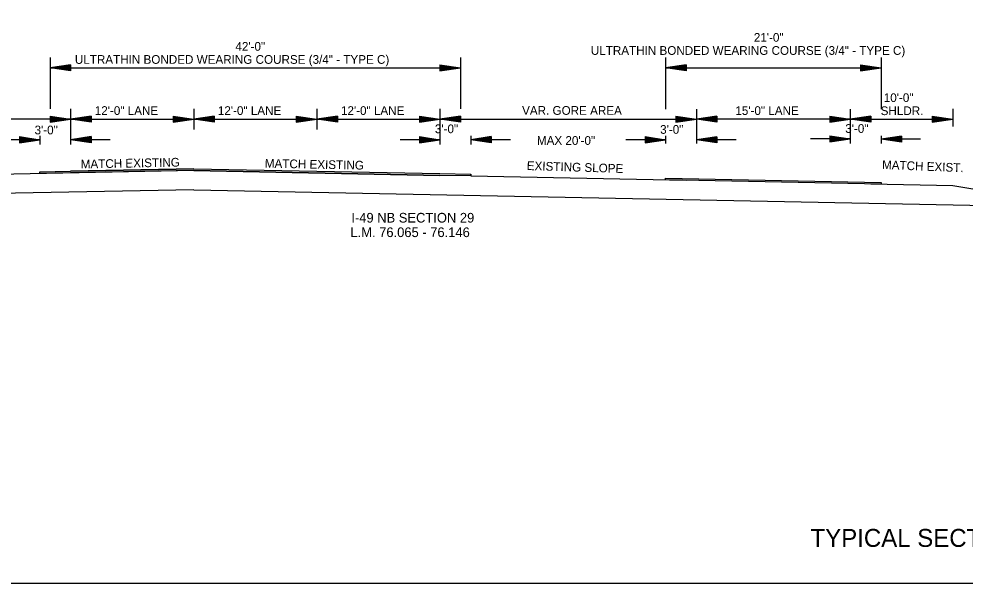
# Model space of a CAD drawing. Extents: x 2261938 to 2263136, y -3124572 to -3124216.
# Drawn here: x 2262374.3 to 2262466.5, y -3124556.1 to -3124501.1 of the extents above; entities that cross this region are included whole.
import ezdxf

# ---------------------------------------------------------------- set-up
doc = ezdxf.new("R2010")
doc.units = 0
for name, color, linetype in [('DSN_DRFT_Common-Annotations', 7, 'Continuous'), ('DSN_DRFT_Common-Line', 7, 'Continuous'), ('DSN_DRFT_Dimension', 7, 'Continuous'), ('SHET_Border-Text', 7, 'Continuous')]:
    doc.layers.add(name, color=color, linetype=linetype)

msp = doc.modelspace()

# ---------------------------------------------------------------- linework, layer by layer
at = {"layer": 'DSN_DRFT_Common-Line'}
for p, q in [((2262377.333, -3124504.876), (2262377.333, -3124509.876)), ((2262417.333, -3124504.876), (2262417.333, -3124509.876)), ((2262437.332, -3124504.876), (2262437.332, -3124509.896)), ((2262458.334, -3124504.876), (2262458.334, -3124509.896)), ((2262379.333, -3124509.876), (2262379.333, -3124513.335)), ((2262391.333, -3124509.876), (2262391.333, -3124511.876)), ((2262403.333, -3124509.876), (2262403.333, -3124511.876)), ((2262415.333, -3124509.876), (2262415.333, -3124513.335)), ((2262465.333, -3124509.876), (2262465.333, -3124511.579)), ((2262440.333, -3124509.896), (2262440.333, -3124513.261)), ((2262455.333, -3124509.896), (2262455.333, -3124513.261)), ((2262376.333, -3124512.495), (2262376.333, -3124513.335)), ((2262418.333, -3124512.495), (2262418.333, -3124513.335)), ((2262437.332, -3124512.495), (2262437.332, -3124513.261)), ((2262458.334, -3124512.495), (2262458.334, -3124513.261)), ((2262391.333, -3124515.876), (2262363.333, -3124516.436)), ((2262391.333, -3124515.71), (2262379.333, -3124515.95)), ((2262391.333, -3124515.71), (2262415.333, -3124516.19)), ((2262391.333, -3124515.876), (2262415.333, -3124516.356)), ((2262418.333, -3124516.416), (2262418.333, -3124516.25)), ((2262418.333, -3124516.416), (2262439.333, -3124516.836)), ((2262457.334, -3124517.191), (2262465.333, -3124517.351)), ((2262391.333, -3124517.751), (2262361.333, -3124518.351)), ((2262391.333, -3124517.751), (2262478.157, -3124519.488)), ((2262465.333, -3124517.351), (2262485.333, -3124520.684))]:
    msp.add_line(p, q, dxfattribs=at)
for points in [[(2262328.106, -3124446.104), (2262328.106, -3124556.104), (2262498.106, -3124556.104), (2262498.106, -3124446.104)], [(2262415.333, -3124516.356), (2262391.333, -3124515.876), (2262379.333, -3124516.116), (2262376.333, -3124516.176), (2262376.333, -3124516.01), (2262379.333, -3124515.95), (2262391.333, -3124515.71), (2262415.333, -3124516.19), (2262418.333, -3124516.25), (2262418.333, -3124516.416)], [(2262458.334, -3124517.211), (2262437.332, -3124516.796), (2262437.332, -3124516.796), (2262437.332, -3124516.796), (2262437.332, -3124516.63), (2262437.332, -3124516.63), (2262437.332, -3124516.63), (2262458.334, -3124517.044), (2262458.334, -3124517.044), (2262458.334, -3124517.211)]]:
    msp.add_lwpolyline(points, close=True, dxfattribs=at)
at = {"layer": 'DSN_DRFT_Dimension'}
for p, q in [((2262379.333, -3124505.576), (2262377.333, -3124505.876)), ((2262379.333, -3124506.176), (2262377.333, -3124505.876)), ((2262377.333, -3124505.876), (2262417.333, -3124505.876)), ((2262379.333, -3124505.626), (2262377.667, -3124505.876)), ((2262379.333, -3124506.126), (2262377.667, -3124505.876)), ((2262379.333, -3124505.677), (2262378.011, -3124505.876)), ((2262379.333, -3124506.075), (2262378.011, -3124505.876)), ((2262379.333, -3124505.727), (2262378.344, -3124505.876)), ((2262379.333, -3124506.025), (2262378.344, -3124505.876)), ((2262379.333, -3124505.779), (2262378.683, -3124505.876)), ((2262379.333, -3124505.974), (2262378.683, -3124505.876)), ((2262379.333, -3124505.829), (2262379.017, -3124505.876)), ((2262379.333, -3124505.923), (2262379.017, -3124505.876)), ((2262379.333, -3124505.576), (2262379.333, -3124506.176)), ((2262415.333, -3124505.576), (2262417.333, -3124505.876)), ((2262415.333, -3124505.576), (2262415.333, -3124506.176)), ((2262415.333, -3124505.626), (2262416.999, -3124505.876)), ((2262415.333, -3124505.677), (2262416.655, -3124505.876)), ((2262415.333, -3124505.727), (2262416.322, -3124505.876)), ((2262415.333, -3124505.779), (2262415.983, -3124505.876)), ((2262415.333, -3124505.829), (2262415.649, -3124505.876)), ((2262415.333, -3124506.176), (2262417.333, -3124505.876)), ((2262415.333, -3124505.974), (2262415.983, -3124505.876)), ((2262415.333, -3124506.075), (2262416.655, -3124505.876)), ((2262415.333, -3124506.126), (2262416.999, -3124505.876)), ((2262415.333, -3124506.025), (2262416.322, -3124505.876)), ((2262415.333, -3124505.923), (2262415.649, -3124505.876)), ((2262439.332, -3124505.576), (2262437.332, -3124505.876)), ((2262437.332, -3124505.876), (2262458.334, -3124505.876)), ((2262439.332, -3124506.176), (2262437.332, -3124505.876)), ((2262439.332, -3124505.626), (2262437.666, -3124505.876)), ((2262439.332, -3124506.126), (2262437.666, -3124505.876)), ((2262439.332, -3124505.677), (2262438.01, -3124505.876)), ((2262439.332, -3124506.075), (2262438.01, -3124505.876)), ((2262439.332, -3124505.727), (2262438.343, -3124505.876)), ((2262439.332, -3124506.025), (2262438.343, -3124505.876)), ((2262439.332, -3124505.779), (2262438.682, -3124505.876)), ((2262439.332, -3124505.974), (2262438.682, -3124505.876)), ((2262439.332, -3124505.829), (2262439.016, -3124505.876)), ((2262439.332, -3124505.923), (2262439.016, -3124505.876)), ((2262439.332, -3124505.576), (2262439.332, -3124506.176)), ((2262456.334, -3124505.576), (2262458.334, -3124505.876)), ((2262456.334, -3124505.576), (2262456.334, -3124506.176)), ((2262456.334, -3124505.626), (2262458, -3124505.876)), ((2262456.334, -3124505.677), (2262457.656, -3124505.876)), ((2262456.334, -3124505.727), (2262457.323, -3124505.876)), ((2262456.334, -3124505.779), (2262456.984, -3124505.876)), ((2262456.334, -3124505.829), (2262456.65, -3124505.876)), ((2262456.334, -3124506.176), (2262458.334, -3124505.876)), ((2262456.334, -3124505.974), (2262456.984, -3124505.876)), ((2262456.334, -3124506.075), (2262457.656, -3124505.876)), ((2262456.334, -3124506.126), (2262458, -3124505.876)), ((2262456.334, -3124506.025), (2262457.323, -3124505.876)), ((2262456.334, -3124505.923), (2262456.65, -3124505.876)), ((2262377.333, -3124510.576), (2262379.333, -3124510.876)), ((2262377.333, -3124510.576), (2262377.333, -3124511.176)), ((2262377.333, -3124510.626), (2262378.999, -3124510.876)), ((2262377.333, -3124510.677), (2262378.655, -3124510.876)), ((2262377.333, -3124510.727), (2262378.322, -3124510.876)), ((2262377.333, -3124510.779), (2262377.983, -3124510.876)), ((2262381.333, -3124510.576), (2262379.333, -3124510.876)), ((2262381.333, -3124510.626), (2262379.667, -3124510.876)), ((2262381.333, -3124510.677), (2262380.011, -3124510.876)), ((2262381.333, -3124510.727), (2262380.344, -3124510.876)), ((2262381.333, -3124510.779), (2262380.683, -3124510.876)), ((2262381.333, -3124510.576), (2262381.333, -3124511.176)), ((2262389.333, -3124510.576), (2262391.333, -3124510.876)), ((2262389.333, -3124510.576), (2262389.333, -3124511.176)), ((2262389.333, -3124510.626), (2262390.999, -3124510.876)), ((2262389.333, -3124510.677), (2262390.655, -3124510.876)), ((2262389.333, -3124510.727), (2262390.322, -3124510.876)), ((2262389.333, -3124510.779), (2262389.983, -3124510.876)), ((2262393.333, -3124510.576), (2262391.333, -3124510.876)), ((2262393.333, -3124510.626), (2262391.667, -3124510.876)), ((2262393.333, -3124510.677), (2262392.011, -3124510.876)), ((2262393.333, -3124510.727), (2262392.344, -3124510.876)), ((2262393.333, -3124510.779), (2262392.683, -3124510.876)), ((2262393.333, -3124510.576), (2262393.333, -3124511.176)), ((2262401.333, -3124510.576), (2262403.333, -3124510.876)), ((2262401.333, -3124510.576), (2262401.333, -3124511.176)), ((2262401.333, -3124510.626), (2262402.999, -3124510.876)), ((2262401.333, -3124510.677), (2262402.655, -3124510.876)), ((2262401.333, -3124510.727), (2262402.322, -3124510.876)), ((2262401.333, -3124510.779), (2262401.983, -3124510.876)), ((2262405.333, -3124510.576), (2262403.333, -3124510.876)), ((2262405.333, -3124510.626), (2262403.667, -3124510.876)), ((2262405.333, -3124510.677), (2262404.011, -3124510.876)), ((2262405.333, -3124510.727), (2262404.344, -3124510.876)), ((2262405.333, -3124510.779), (2262404.683, -3124510.876)), ((2262405.333, -3124510.576), (2262405.333, -3124511.176)), ((2262413.333, -3124510.576), (2262415.333, -3124510.876)), ((2262413.333, -3124510.576), (2262413.333, -3124511.176)), ((2262413.333, -3124510.626), (2262414.999, -3124510.876)), ((2262413.333, -3124510.677), (2262414.655, -3124510.876)), ((2262413.333, -3124510.727), (2262414.322, -3124510.876)), ((2262413.333, -3124510.779), (2262413.983, -3124510.876)), ((2262417.333, -3124510.576), (2262415.333, -3124510.876)), ((2262417.333, -3124510.626), (2262415.667, -3124510.876)), ((2262417.333, -3124510.677), (2262416.011, -3124510.876)), ((2262417.333, -3124510.727), (2262416.344, -3124510.876)), ((2262417.333, -3124510.779), (2262416.683, -3124510.876)), ((2262417.333, -3124510.576), (2262417.333, -3124511.176)), ((2262438.333, -3124510.576), (2262440.333, -3124510.876)), ((2262438.333, -3124510.576), (2262438.333, -3124511.176)), ((2262438.333, -3124510.626), (2262439.999, -3124510.876)), ((2262438.333, -3124510.677), (2262439.655, -3124510.876)), ((2262438.333, -3124510.727), (2262439.322, -3124510.876)), ((2262438.333, -3124510.779), (2262438.983, -3124510.876)), ((2262442.333, -3124510.576), (2262440.333, -3124510.876)), ((2262442.333, -3124510.626), (2262440.667, -3124510.876)), ((2262442.333, -3124510.677), (2262441.011, -3124510.876)), ((2262442.333, -3124510.727), (2262441.344, -3124510.876)), ((2262442.333, -3124510.779), (2262441.683, -3124510.876)), ((2262442.333, -3124510.576), (2262442.333, -3124511.176)), ((2262453.333, -3124510.576), (2262455.333, -3124510.876)), ((2262453.333, -3124510.576), (2262453.333, -3124511.176)), ((2262453.333, -3124510.626), (2262454.999, -3124510.876)), ((2262453.333, -3124510.677), (2262454.655, -3124510.876)), ((2262453.333, -3124510.727), (2262454.322, -3124510.876)), ((2262453.333, -3124510.779), (2262453.983, -3124510.876)), ((2262457.333, -3124510.576), (2262455.333, -3124510.876)), ((2262457.333, -3124510.626), (2262455.667, -3124510.876)), ((2262457.333, -3124510.677), (2262456.011, -3124510.876)), ((2262457.333, -3124510.727), (2262456.344, -3124510.876)), ((2262457.333, -3124510.779), (2262456.683, -3124510.876)), ((2262457.333, -3124510.576), (2262457.333, -3124511.176)), ((2262463.333, -3124510.576), (2262465.333, -3124510.876)), ((2262463.333, -3124510.576), (2262463.333, -3124511.176)), ((2262463.333, -3124510.626), (2262464.999, -3124510.876)), ((2262463.333, -3124510.677), (2262464.655, -3124510.876)), ((2262463.333, -3124510.727), (2262464.322, -3124510.876)), ((2262463.333, -3124510.779), (2262463.983, -3124510.876)), ((2262379.333, -3124510.876), (2262361.333, -3124510.876)), ((2262377.333, -3124510.829), (2262377.649, -3124510.876)), ((2262377.333, -3124511.176), (2262379.333, -3124510.876)), ((2262377.333, -3124510.974), (2262377.983, -3124510.876)), ((2262377.333, -3124511.075), (2262378.655, -3124510.876)), ((2262377.333, -3124511.126), (2262378.999, -3124510.876)), ((2262377.333, -3124511.025), (2262378.322, -3124510.876)), ((2262377.333, -3124510.923), (2262377.649, -3124510.876)), ((2262379.333, -3124510.876), (2262391.333, -3124510.876)), ((2262381.333, -3124511.176), (2262379.333, -3124510.876)), ((2262381.333, -3124511.126), (2262379.667, -3124510.876)), ((2262381.333, -3124511.075), (2262380.011, -3124510.876)), ((2262381.333, -3124511.025), (2262380.344, -3124510.876)), ((2262381.333, -3124510.974), (2262380.683, -3124510.876)), ((2262381.333, -3124510.829), (2262381.017, -3124510.876)), ((2262381.333, -3124510.923), (2262381.017, -3124510.876)), ((2262389.333, -3124510.829), (2262389.649, -3124510.876)), ((2262389.333, -3124511.176), (2262391.333, -3124510.876)), ((2262389.333, -3124510.974), (2262389.983, -3124510.876)), ((2262389.333, -3124511.075), (2262390.655, -3124510.876)), ((2262389.333, -3124511.126), (2262390.999, -3124510.876)), ((2262389.333, -3124511.025), (2262390.322, -3124510.876)), ((2262389.333, -3124510.923), (2262389.649, -3124510.876)), ((2262391.333, -3124510.876), (2262403.333, -3124510.876)), ((2262393.333, -3124511.176), (2262391.333, -3124510.876)), ((2262393.333, -3124511.126), (2262391.667, -3124510.876)), ((2262393.333, -3124511.075), (2262392.011, -3124510.876)), ((2262393.333, -3124511.025), (2262392.344, -3124510.876)), ((2262393.333, -3124510.974), (2262392.683, -3124510.876)), ((2262393.333, -3124510.829), (2262393.017, -3124510.876)), ((2262393.333, -3124510.923), (2262393.017, -3124510.876)), ((2262401.333, -3124510.829), (2262401.649, -3124510.876)), ((2262401.333, -3124511.176), (2262403.333, -3124510.876)), ((2262401.333, -3124510.974), (2262401.983, -3124510.876)), ((2262401.333, -3124511.075), (2262402.655, -3124510.876)), ((2262401.333, -3124511.126), (2262402.999, -3124510.876)), ((2262401.333, -3124511.025), (2262402.322, -3124510.876)), ((2262401.333, -3124510.923), (2262401.649, -3124510.876)), ((2262403.333, -3124510.876), (2262415.333, -3124510.876)), ((2262405.333, -3124511.176), (2262403.333, -3124510.876)), ((2262405.333, -3124511.126), (2262403.667, -3124510.876)), ((2262405.333, -3124511.075), (2262404.011, -3124510.876)), ((2262405.333, -3124511.025), (2262404.344, -3124510.876)), ((2262405.333, -3124510.974), (2262404.683, -3124510.876)), ((2262405.333, -3124510.829), (2262405.017, -3124510.876)), ((2262405.333, -3124510.923), (2262405.017, -3124510.876)), ((2262413.333, -3124510.829), (2262413.649, -3124510.876)), ((2262413.333, -3124511.176), (2262415.333, -3124510.876)), ((2262413.333, -3124510.974), (2262413.983, -3124510.876)), ((2262413.333, -3124511.075), (2262414.655, -3124510.876)), ((2262413.333, -3124511.126), (2262414.999, -3124510.876)), ((2262413.333, -3124511.025), (2262414.322, -3124510.876)), ((2262413.333, -3124510.923), (2262413.649, -3124510.876)), ((2262415.333, -3124510.876), (2262440.333, -3124510.876)), ((2262417.333, -3124511.176), (2262415.333, -3124510.876)), ((2262417.333, -3124511.126), (2262415.667, -3124510.876)), ((2262417.333, -3124511.075), (2262416.011, -3124510.876)), ((2262417.333, -3124511.025), (2262416.344, -3124510.876)), ((2262417.333, -3124510.974), (2262416.683, -3124510.876)), ((2262417.333, -3124510.829), (2262417.017, -3124510.876)), ((2262417.333, -3124510.923), (2262417.017, -3124510.876)), ((2262438.333, -3124510.829), (2262438.649, -3124510.876)), ((2262438.333, -3124511.176), (2262440.333, -3124510.876)), ((2262438.333, -3124510.974), (2262438.983, -3124510.876)), ((2262438.333, -3124511.075), (2262439.655, -3124510.876)), ((2262438.333, -3124511.126), (2262439.999, -3124510.876)), ((2262438.333, -3124511.025), (2262439.322, -3124510.876)), ((2262438.333, -3124510.923), (2262438.649, -3124510.876)), ((2262455.333, -3124510.876), (2262440.333, -3124510.876)), ((2262442.333, -3124511.176), (2262440.333, -3124510.876)), ((2262442.333, -3124511.126), (2262440.667, -3124510.876)), ((2262442.333, -3124511.075), (2262441.011, -3124510.876)), ((2262442.333, -3124511.025), (2262441.344, -3124510.876)), ((2262442.333, -3124510.974), (2262441.683, -3124510.876)), ((2262442.333, -3124510.829), (2262442.017, -3124510.876)), ((2262442.333, -3124510.923), (2262442.017, -3124510.876)), ((2262453.333, -3124510.829), (2262453.649, -3124510.876)), ((2262453.333, -3124511.176), (2262455.333, -3124510.876)), ((2262453.333, -3124510.974), (2262453.983, -3124510.876)), ((2262453.333, -3124511.075), (2262454.655, -3124510.876)), ((2262453.333, -3124511.126), (2262454.999, -3124510.876)), ((2262453.333, -3124511.025), (2262454.322, -3124510.876)), ((2262453.333, -3124510.923), (2262453.649, -3124510.876)), ((2262455.333, -3124510.876), (2262465.333, -3124510.876)), ((2262457.333, -3124511.176), (2262455.333, -3124510.876)), ((2262457.333, -3124511.126), (2262455.667, -3124510.876)), ((2262457.333, -3124511.075), (2262456.011, -3124510.876)), ((2262457.333, -3124511.025), (2262456.344, -3124510.876)), ((2262457.333, -3124510.974), (2262456.683, -3124510.876)), ((2262457.333, -3124510.829), (2262457.017, -3124510.876)), ((2262457.333, -3124510.923), (2262457.017, -3124510.876)), ((2262463.333, -3124510.829), (2262463.649, -3124510.876)), ((2262463.333, -3124511.176), (2262465.333, -3124510.876)), ((2262463.333, -3124510.974), (2262463.983, -3124510.876)), ((2262463.333, -3124511.075), (2262464.655, -3124510.876)), ((2262463.333, -3124511.126), (2262464.999, -3124510.876)), ((2262463.333, -3124511.025), (2262464.322, -3124510.876)), ((2262463.333, -3124510.923), (2262463.649, -3124510.876)), ((2262374.333, -3124512.576), (2262376.333, -3124512.876)), ((2262374.333, -3124512.576), (2262374.333, -3124513.176)), ((2262374.333, -3124512.626), (2262375.999, -3124512.876)), ((2262381.333, -3124512.576), (2262379.333, -3124512.876)), ((2262381.333, -3124512.626), (2262379.667, -3124512.876)), ((2262381.333, -3124512.576), (2262381.333, -3124513.176)), ((2262413.333, -3124512.576), (2262415.333, -3124512.876)), ((2262413.333, -3124512.576), (2262413.333, -3124513.176)), ((2262413.333, -3124512.626), (2262414.999, -3124512.876)), ((2262420.333, -3124512.576), (2262418.333, -3124512.876)), ((2262420.333, -3124512.626), (2262418.667, -3124512.876)), ((2262420.333, -3124512.576), (2262420.333, -3124513.176)), ((2262435.332, -3124512.576), (2262437.332, -3124512.876)), ((2262435.332, -3124512.576), (2262435.332, -3124513.176)), ((2262435.332, -3124512.626), (2262436.998, -3124512.876)), ((2262442.333, -3124512.596), (2262440.333, -3124512.896)), ((2262442.333, -3124512.646), (2262440.667, -3124512.896)), ((2262442.333, -3124512.596), (2262442.333, -3124513.196)), ((2262453.333, -3124512.502), (2262455.333, -3124512.802)), ((2262453.333, -3124512.502), (2262453.333, -3124513.102)), ((2262453.333, -3124512.552), (2262454.999, -3124512.802)), ((2262453.333, -3124512.603), (2262454.655, -3124512.802)), ((2262453.333, -3124512.653), (2262454.322, -3124512.802)), ((2262460.334, -3124512.522), (2262458.334, -3124512.822)), ((2262460.334, -3124512.572), (2262458.668, -3124512.822)), ((2262460.334, -3124512.623), (2262459.012, -3124512.822)), ((2262460.334, -3124512.522), (2262460.334, -3124513.122)), ((2262376.333, -3124512.876), (2262372.468, -3124512.876)), ((2262374.333, -3124512.677), (2262375.655, -3124512.876)), ((2262374.333, -3124512.727), (2262375.322, -3124512.876)), ((2262374.333, -3124512.779), (2262374.983, -3124512.876)), ((2262374.333, -3124512.829), (2262374.649, -3124512.876)), ((2262374.333, -3124513.176), (2262376.333, -3124512.876)), ((2262374.333, -3124512.974), (2262374.983, -3124512.876)), ((2262374.333, -3124513.075), (2262375.655, -3124512.876)), ((2262374.333, -3124513.126), (2262375.999, -3124512.876)), ((2262374.333, -3124513.025), (2262375.322, -3124512.876)), ((2262374.333, -3124512.923), (2262374.649, -3124512.876)), ((2262381.333, -3124513.176), (2262379.333, -3124512.876)), ((2262383.198, -3124512.876), (2262379.333, -3124512.876)), ((2262381.333, -3124513.126), (2262379.667, -3124512.876)), ((2262381.333, -3124512.677), (2262380.011, -3124512.876)), ((2262381.333, -3124513.075), (2262380.011, -3124512.876)), ((2262381.333, -3124512.727), (2262380.344, -3124512.876)), ((2262381.333, -3124513.025), (2262380.344, -3124512.876)), ((2262381.333, -3124512.779), (2262380.683, -3124512.876)), ((2262381.333, -3124512.974), (2262380.683, -3124512.876)), ((2262381.333, -3124512.829), (2262381.017, -3124512.876)), ((2262381.333, -3124512.923), (2262381.017, -3124512.876)), ((2262415.333, -3124512.876), (2262411.468, -3124512.876)), ((2262413.333, -3124512.677), (2262414.655, -3124512.876)), ((2262413.333, -3124512.727), (2262414.322, -3124512.876)), ((2262413.333, -3124512.779), (2262413.983, -3124512.876)), ((2262413.333, -3124512.829), (2262413.649, -3124512.876)), ((2262413.333, -3124513.176), (2262415.333, -3124512.876)), ((2262413.333, -3124512.974), (2262413.983, -3124512.876)), ((2262413.333, -3124513.075), (2262414.655, -3124512.876)), ((2262413.333, -3124513.126), (2262414.999, -3124512.876)), ((2262413.333, -3124513.025), (2262414.322, -3124512.876)), ((2262413.333, -3124512.923), (2262413.649, -3124512.876)), ((2262420.333, -3124513.176), (2262418.333, -3124512.876)), ((2262422.198, -3124512.876), (2262418.333, -3124512.876)), ((2262420.333, -3124513.126), (2262418.667, -3124512.876)), ((2262420.333, -3124512.677), (2262419.011, -3124512.876)), ((2262420.333, -3124513.075), (2262419.011, -3124512.876)), ((2262420.333, -3124512.727), (2262419.344, -3124512.876)), ((2262420.333, -3124513.025), (2262419.344, -3124512.876)), ((2262420.333, -3124512.779), (2262419.683, -3124512.876)), ((2262420.333, -3124512.974), (2262419.683, -3124512.876)), ((2262420.333, -3124512.829), (2262420.017, -3124512.876)), ((2262420.333, -3124512.923), (2262420.017, -3124512.876)), ((2262437.332, -3124512.876), (2262433.467, -3124512.876)), ((2262435.332, -3124512.677), (2262436.654, -3124512.876)), ((2262435.332, -3124512.727), (2262436.321, -3124512.876)), ((2262435.332, -3124512.779), (2262435.982, -3124512.876)), ((2262435.332, -3124512.829), (2262435.648, -3124512.876)), ((2262435.332, -3124513.176), (2262437.332, -3124512.876)), ((2262435.332, -3124512.974), (2262435.982, -3124512.876)), ((2262435.332, -3124513.075), (2262436.654, -3124512.876)), ((2262435.332, -3124513.126), (2262436.998, -3124512.876)), ((2262435.332, -3124513.025), (2262436.321, -3124512.876)), ((2262435.332, -3124512.923), (2262435.648, -3124512.876)), ((2262442.333, -3124513.196), (2262440.333, -3124512.896)), ((2262444.198, -3124512.896), (2262440.333, -3124512.896)), ((2262442.333, -3124513.146), (2262440.667, -3124512.896)), ((2262442.333, -3124512.697), (2262441.011, -3124512.896)), ((2262442.333, -3124513.095), (2262441.011, -3124512.896)), ((2262442.333, -3124512.747), (2262441.344, -3124512.896)), ((2262442.333, -3124513.045), (2262441.344, -3124512.896)), ((2262442.333, -3124512.799), (2262441.683, -3124512.896)), ((2262442.333, -3124512.994), (2262441.683, -3124512.896)), ((2262442.333, -3124512.849), (2262442.017, -3124512.896)), ((2262442.333, -3124512.943), (2262442.017, -3124512.896)), ((2262455.333, -3124512.802), (2262451.468, -3124512.802)), ((2262453.333, -3124512.705), (2262453.983, -3124512.802)), ((2262453.333, -3124512.755), (2262453.649, -3124512.802)), ((2262453.333, -3124513.102), (2262455.333, -3124512.802)), ((2262453.333, -3124512.9), (2262453.983, -3124512.802)), ((2262453.333, -3124513.001), (2262454.655, -3124512.802)), ((2262453.333, -3124513.052), (2262454.999, -3124512.802)), ((2262453.333, -3124512.951), (2262454.322, -3124512.802)), ((2262453.333, -3124512.849), (2262453.649, -3124512.802)), ((2262460.334, -3124513.122), (2262458.334, -3124512.822)), ((2262462.199, -3124512.822), (2262458.334, -3124512.822)), ((2262460.334, -3124513.072), (2262458.668, -3124512.822)), ((2262460.334, -3124513.021), (2262459.012, -3124512.822)), ((2262460.334, -3124512.673), (2262459.345, -3124512.822)), ((2262460.334, -3124512.971), (2262459.345, -3124512.822)), ((2262460.334, -3124512.725), (2262459.684, -3124512.822)), ((2262460.334, -3124512.92), (2262459.684, -3124512.822)), ((2262460.334, -3124512.775), (2262460.018, -3124512.822)), ((2262460.334, -3124512.869), (2262460.018, -3124512.822))]:
    msp.add_line(p, q, dxfattribs=at)

# ---------------------------------------------------------------- texts
at = {"layer": 'DSN_DRFT_Common-Annotations'}
for s, height, p in [('21\'-0"', 0.85, (2262445.937, -3124503.331)), ('42\'-0"', 0.85, (2262395.395, -3124504.206)), ('ULTRATHIN BONDED WEARING COURSE (3/4" - TYPE C)', 0.85, (2262430.045, -3124504.606)), ('ULTRATHIN BONDED WEARING COURSE (3/4" - TYPE C)', 0.85, (2262379.744, -3124505.481)), ('10\'-0"', 0.85, (2262458.603, -3124509.206)), ('12\'-0" LANE', 0.85, (2262381.685, -3124510.466)), ('12\'-0" LANE', 0.85, (2262393.685, -3124510.466)), ('12\'-0" LANE', 0.85, (2262405.685, -3124510.466)), ('VAR. GORE AREA', 0.85, (2262423.342, -3124510.452)), ('15\'-0" LANE', 0.85, (2262444.134, -3124510.466)), ('SHLDR.', 0.85, (2262458.298, -3124510.481)), (' 3\'-0"', 0.85, (2262375.498, -3124512.357)), (' 3\'-0"', 0.85, (2262414.526, -3124512.243)), (' 3\'-0"', 0.85, (2262436.486, -3124512.303)), (' 3\'-0"', 0.85, (2262454.53, -3124512.215)), ('MAX 20\'-0"', 0.85, (2262424.788, -3124513.382)), ('I-49 NB SECTION 29', 0.943, (2262406.697, -3124520.958)), ('L.M. 76.065 - 76.146', 0.943, (2262406.608, -3124522.373))]:
    msp.add_text(s, height=height, dxfattribs=at).set_placement(p)
for s, rotation, p in [('MATCH EXISTING', 1.14576, (2262380.323, -3124515.687)), ('MATCH EXISTING', 358.85424, (2262398.254, -3124515.605)), ('EXISTING SLOPE', 358.23112, (2262423.789, -3124515.833)), ('MATCH EXIST.', 357.70939, (2262458.419, -3124515.732))]:
    msp.add_text(s, height=0.85, rotation=rotation, dxfattribs=at).set_placement(p)
at = {"layer": 'SHET_Border-Text'}
msp.add_text('TYPICAL SECTIONS OF IMPROVEMENT', height=1.75, dxfattribs=at).set_placement((2262451.462, -3124552.576))

doc.saveas('drawing.dxf')
